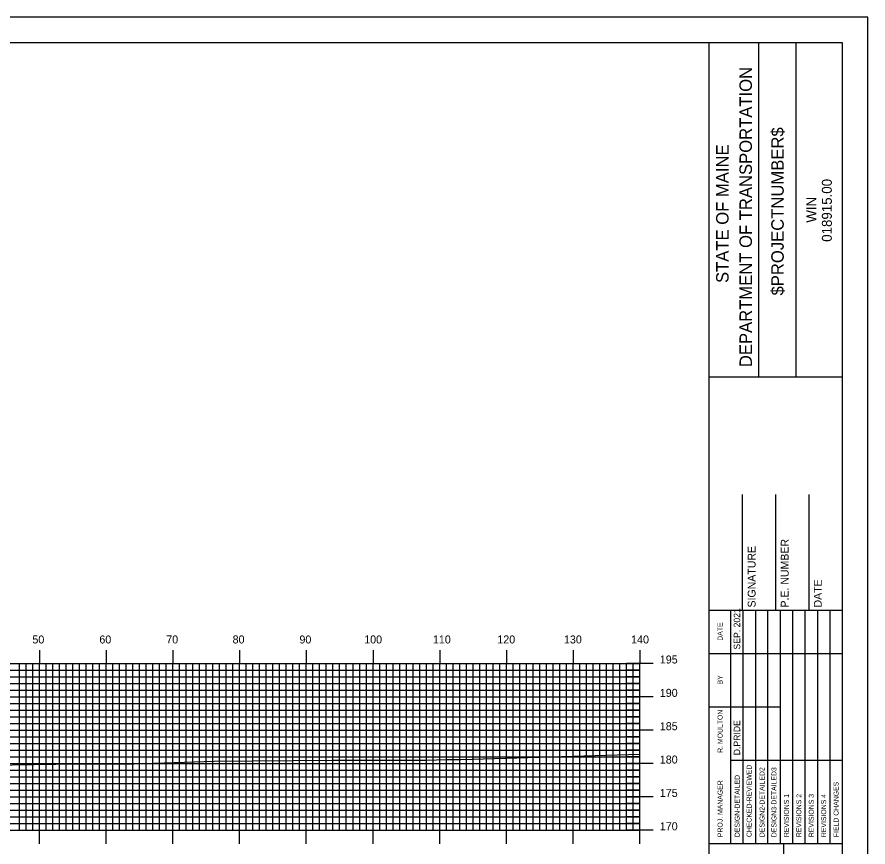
# Model space of a CAD drawing. Extents: x 1823573 to 1823916, y 442591 to 442811.
# Drawn here: x 1823784.9 to 1823912.5, y 442686.2 to 442810.5 of the extents above; entities that cross this region are included whole.
import ezdxf

# ---------------------------------------------------------------- set-up
doc = ezdxf.new("R2010")
doc.units = 0
for name, color, linetype in [('BORDER', 7, 'Continuous'), ('H_V ANNOTATION', 7, 'Continuous'), ('MAJOR', 7, 'Continuous'), ('MINOR', 7, 'Continuous'), ('PLOT BOUNDARY', 7, 'Continuous'), ('S_Roadway_Centerline', 7, 'Continuous')]:
    doc.layers.add(name, color=color, linetype=linetype)

msp = doc.modelspace()

# ---------------------------------------------------------------- linework, layer by layer
at = {"layer": 'BORDER'}
for p, q in [((1823888.71, 442596.67), (1823888.71, 442806.67)), ((1823896.17, 442756.66), (1823896.17, 442806.66)), ((1823901.76, 442756.66), (1823901.76, 442806.66)), ((1823888.71, 442756.65), (1823908.71, 442756.65)), ((1823893.71, 442721.67), (1823893.71, 442738.97)), ((1823898.71, 442721.67), (1823898.71, 442738.97)), ((1823903.71, 442721.67), (1823903.71, 442738.97)), ((1823888.71, 442721.67), (1823908.71, 442721.67)), ((1823888.71, 442686.67), (1823908.71, 442686.67)), ((1823899.89, 442616.67), (1823899.89, 442686.67))]:
    msp.add_line(p, q, dxfattribs=at)
msp.add_lwpolyline([(1823588.71, 442596.67), (1823908.71, 442596.67), (1823908.71, 442806.67), (1823588.71, 442806.67)], close=True, dxfattribs=at)
for points in [[(1823891.94, 442715.17), (1823891.94, 442721.67)], [(1823893.8, 442686.68), (1823893.8, 442721.67)], [(1823895.67, 442721.67), (1823895.67, 442686.68)], [(1823897.53, 442686.68), (1823897.53, 442721.67)], [(1823899.39, 442686.68), (1823899.39, 442721.67)], [(1823901.26, 442686.68), (1823901.26, 442721.67)], [(1823903.12, 442686.68), (1823903.12, 442721.67)], [(1823904.98, 442686.68), (1823904.98, 442721.67)], [(1823906.85, 442686.68), (1823906.85, 442721.67)], [(1823891.94, 442686.68), (1823891.94, 442720.26)], [(1823888.71, 442715.17), (1823908.71, 442715.17)], [(1823888.71, 442707.17), (1823891.94, 442707.17)], [(1823891.94, 442707.17), (1823899.39, 442707.17)], [(1823891.94, 442699.17), (1823908.71, 442699.17)]]:
    msp.add_lwpolyline(points, dxfattribs=at)
at = {"layer": 'MAJOR'}
for p, q in [((1823788.31, 442715.67), (1823788.31, 442713.67)), ((1823798.31, 442715.67), (1823798.31, 442713.67)), ((1823808.31, 442715.67), (1823808.31, 442713.67)), ((1823818.31, 442715.67), (1823818.31, 442713.67)), ((1823828.31, 442715.67), (1823828.31, 442713.67)), ((1823838.31, 442715.67), (1823838.31, 442713.67)), ((1823848.31, 442715.67), (1823848.31, 442713.67)), ((1823858.31, 442715.67), (1823858.31, 442713.67)), ((1823868.31, 442715.67), (1823868.31, 442713.67)), ((1823878.31, 442715.67), (1823878.31, 442713.67)), ((1823598.31, 442713.67), (1823878.31, 442713.67)), ((1823598.31, 442713.67), (1823878.31, 442713.67)), ((1823788.31, 442688.67), (1823788.31, 442713.67)), ((1823798.31, 442688.67), (1823798.31, 442713.67)), ((1823808.31, 442688.67), (1823808.31, 442713.67)), ((1823818.31, 442688.67), (1823818.31, 442713.67)), ((1823828.31, 442688.67), (1823828.31, 442713.67)), ((1823838.31, 442688.67), (1823838.31, 442713.67)), ((1823848.31, 442688.67), (1823848.31, 442713.67)), ((1823858.31, 442688.67), (1823858.31, 442713.67)), ((1823868.31, 442688.67), (1823868.31, 442713.67)), ((1823880.31, 442713.67), (1823876.3, 442713.67)), ((1823878.31, 442688.67), (1823878.31, 442713.67)), ((1823878.31, 442688.67), (1823878.31, 442713.67)), ((1823598.31, 442708.67), (1823878.31, 442708.67)), ((1823880.31, 442708.67), (1823876.3, 442708.67)), ((1823598.31, 442703.67), (1823878.31, 442703.67)), ((1823880.31, 442703.67), (1823876.3, 442703.67)), ((1823598.31, 442698.67), (1823878.31, 442698.67)), ((1823880.31, 442698.67), (1823876.3, 442698.67)), ((1823598.31, 442693.67), (1823878.31, 442693.67)), ((1823880.31, 442693.67), (1823876.3, 442693.67)), ((1823598.31, 442688.67), (1823878.31, 442688.67)), ((1823598.31, 442688.67), (1823878.31, 442688.67)), ((1823788.31, 442686.66), (1823788.31, 442688.67)), ((1823798.31, 442686.66), (1823798.31, 442688.67)), ((1823808.31, 442686.66), (1823808.31, 442688.67)), ((1823818.31, 442686.66), (1823818.31, 442688.67)), ((1823828.31, 442686.66), (1823828.31, 442688.67)), ((1823838.31, 442686.66), (1823838.31, 442688.67)), ((1823848.31, 442686.66), (1823848.31, 442688.67)), ((1823858.31, 442686.66), (1823858.31, 442688.67)), ((1823868.31, 442686.66), (1823868.31, 442688.67)), ((1823880.31, 442688.67), (1823876.3, 442688.67)), ((1823878.31, 442686.66), (1823878.31, 442688.67))]:
    msp.add_line(p, q, dxfattribs=at)
at = {"layer": 'MINOR'}
for p, q in [((1823785.31, 442688.67), (1823785.31, 442713.67)), ((1823786.31, 442688.67), (1823786.31, 442713.67)), ((1823787.31, 442688.67), (1823787.31, 442713.67)), ((1823789.31, 442688.67), (1823789.31, 442713.67)), ((1823790.31, 442688.67), (1823790.31, 442713.67)), ((1823791.31, 442688.67), (1823791.31, 442713.67)), ((1823792.31, 442688.67), (1823792.31, 442713.67)), ((1823793.31, 442688.67), (1823793.31, 442713.67)), ((1823794.31, 442688.67), (1823794.31, 442713.67)), ((1823795.31, 442688.67), (1823795.31, 442713.67)), ((1823796.31, 442688.67), (1823796.31, 442713.67)), ((1823797.31, 442688.67), (1823797.31, 442713.67)), ((1823799.31, 442688.67), (1823799.31, 442713.67)), ((1823800.31, 442688.67), (1823800.31, 442713.67)), ((1823801.31, 442688.67), (1823801.31, 442713.67)), ((1823802.31, 442688.67), (1823802.31, 442713.67)), ((1823803.31, 442688.67), (1823803.31, 442713.67)), ((1823804.31, 442688.67), (1823804.31, 442713.67)), ((1823805.31, 442688.67), (1823805.31, 442713.67)), ((1823806.31, 442688.67), (1823806.31, 442713.67)), ((1823807.31, 442688.67), (1823807.31, 442713.67)), ((1823809.31, 442688.67), (1823809.31, 442713.67)), ((1823810.31, 442688.67), (1823810.31, 442713.67)), ((1823811.31, 442688.67), (1823811.31, 442713.67)), ((1823812.31, 442688.67), (1823812.31, 442713.67)), ((1823813.31, 442688.67), (1823813.31, 442713.67)), ((1823814.31, 442688.67), (1823814.31, 442713.67)), ((1823815.31, 442688.67), (1823815.31, 442713.67)), ((1823816.31, 442688.67), (1823816.31, 442713.67)), ((1823817.31, 442688.67), (1823817.31, 442713.67)), ((1823819.31, 442688.67), (1823819.31, 442713.67)), ((1823820.31, 442688.67), (1823820.31, 442713.67)), ((1823821.31, 442688.67), (1823821.31, 442713.67)), ((1823822.31, 442688.67), (1823822.31, 442713.67)), ((1823823.31, 442688.67), (1823823.31, 442713.67)), ((1823824.31, 442688.67), (1823824.31, 442713.67)), ((1823825.31, 442688.67), (1823825.31, 442713.67)), ((1823826.31, 442688.67), (1823826.31, 442713.67)), ((1823827.31, 442688.67), (1823827.31, 442713.67)), ((1823829.31, 442688.67), (1823829.31, 442713.67)), ((1823830.31, 442688.67), (1823830.31, 442713.67)), ((1823831.31, 442688.67), (1823831.31, 442713.67)), ((1823832.31, 442688.67), (1823832.31, 442713.67)), ((1823833.31, 442688.67), (1823833.31, 442713.67)), ((1823834.31, 442688.67), (1823834.31, 442713.67)), ((1823835.31, 442688.67), (1823835.31, 442713.67)), ((1823836.31, 442688.67), (1823836.31, 442713.67)), ((1823837.31, 442688.67), (1823837.31, 442713.67)), ((1823839.31, 442688.67), (1823839.31, 442713.67)), ((1823840.31, 442688.67), (1823840.31, 442713.67)), ((1823841.31, 442688.67), (1823841.31, 442713.67)), ((1823842.31, 442688.67), (1823842.31, 442713.67)), ((1823843.31, 442688.67), (1823843.31, 442713.67)), ((1823844.31, 442688.67), (1823844.31, 442713.67)), ((1823845.31, 442688.67), (1823845.31, 442713.67)), ((1823846.31, 442688.67), (1823846.31, 442713.67)), ((1823847.31, 442688.67), (1823847.31, 442713.67)), ((1823849.31, 442688.67), (1823849.31, 442713.67)), ((1823850.31, 442688.67), (1823850.31, 442713.67)), ((1823851.31, 442688.67), (1823851.31, 442713.67)), ((1823852.31, 442688.67), (1823852.31, 442713.67)), ((1823853.31, 442688.67), (1823853.31, 442713.67)), ((1823854.31, 442688.67), (1823854.31, 442713.67)), ((1823855.31, 442688.67), (1823855.31, 442713.67)), ((1823856.31, 442688.67), (1823856.31, 442713.67)), ((1823857.31, 442688.67), (1823857.31, 442713.67)), ((1823859.31, 442688.67), (1823859.31, 442713.67)), ((1823860.31, 442688.67), (1823860.31, 442713.67)), ((1823861.31, 442688.67), (1823861.31, 442713.67)), ((1823862.31, 442688.67), (1823862.31, 442713.67)), ((1823863.31, 442688.67), (1823863.31, 442713.67)), ((1823864.31, 442688.67), (1823864.31, 442713.67)), ((1823865.31, 442688.67), (1823865.31, 442713.67)), ((1823866.31, 442688.67), (1823866.31, 442713.67)), ((1823867.31, 442688.67), (1823867.31, 442713.67)), ((1823869.31, 442688.67), (1823869.31, 442713.67)), ((1823870.31, 442688.67), (1823870.31, 442713.67)), ((1823871.31, 442688.67), (1823871.31, 442713.67)), ((1823872.31, 442688.67), (1823872.31, 442713.67)), ((1823873.31, 442688.67), (1823873.31, 442713.67)), ((1823874.31, 442688.67), (1823874.31, 442713.67)), ((1823875.31, 442688.67), (1823875.31, 442713.67)), ((1823876.31, 442688.67), (1823876.31, 442713.67)), ((1823877.31, 442688.67), (1823877.31, 442713.67)), ((1823598.31, 442712.67), (1823878.31, 442712.67)), ((1823878.31, 442712.67), (1823876.3, 442712.67)), ((1823598.31, 442711.67), (1823878.31, 442711.67)), ((1823878.31, 442711.67), (1823876.3, 442711.67)), ((1823598.31, 442710.67), (1823878.31, 442710.67)), ((1823878.31, 442710.67), (1823876.3, 442710.67)), ((1823598.31, 442709.67), (1823878.31, 442709.67)), ((1823878.31, 442709.67), (1823876.3, 442709.67)), ((1823598.31, 442707.67), (1823878.31, 442707.67)), ((1823878.31, 442707.67), (1823876.3, 442707.67)), ((1823598.31, 442706.67), (1823878.31, 442706.67)), ((1823878.31, 442706.67), (1823876.3, 442706.67)), ((1823598.31, 442705.67), (1823878.31, 442705.67)), ((1823878.31, 442705.67), (1823876.3, 442705.67)), ((1823598.31, 442704.67), (1823878.31, 442704.67)), ((1823878.31, 442704.67), (1823876.3, 442704.67)), ((1823598.31, 442702.67), (1823878.31, 442702.67)), ((1823878.31, 442702.67), (1823876.3, 442702.67)), ((1823598.31, 442701.67), (1823878.31, 442701.67)), ((1823878.31, 442701.67), (1823876.3, 442701.67)), ((1823598.31, 442700.67), (1823878.31, 442700.67)), ((1823598.31, 442699.67), (1823878.31, 442699.67)), ((1823878.31, 442700.67), (1823876.3, 442700.67)), ((1823878.31, 442699.67), (1823876.3, 442699.67)), ((1823598.31, 442697.67), (1823878.31, 442697.67)), ((1823878.31, 442697.67), (1823876.3, 442697.67)), ((1823598.31, 442696.67), (1823878.31, 442696.67)), ((1823878.31, 442696.67), (1823876.3, 442696.67)), ((1823598.31, 442695.67), (1823878.31, 442695.67)), ((1823598.31, 442694.67), (1823878.31, 442694.67)), ((1823878.31, 442695.67), (1823876.3, 442695.67)), ((1823878.31, 442694.67), (1823876.3, 442694.67)), ((1823598.31, 442692.67), (1823878.31, 442692.67)), ((1823878.31, 442692.67), (1823876.3, 442692.67)), ((1823598.31, 442691.67), (1823878.31, 442691.67)), ((1823598.31, 442690.67), (1823878.31, 442690.67)), ((1823878.31, 442691.67), (1823876.3, 442691.67)), ((1823878.31, 442690.67), (1823876.3, 442690.67)), ((1823598.31, 442689.67), (1823878.31, 442689.67)), ((1823878.31, 442689.67), (1823876.3, 442689.67))]:
    msp.add_line(p, q, dxfattribs=at)
at = {"layer": 'PLOT BOUNDARY'}
msp.add_lwpolyline([(1823572.52, 442590.55), (1823912.52, 442590.55), (1823912.52, 442810.55), (1823572.52, 442810.55)], close=True, dxfattribs=at)
at = {"layer": 'S_Roadway_Centerline'}
msp.add_lwpolyline([(1823774.36, 442698.35), (1823794.06, 442698.63), (1823802.46, 442698.65), (1823806.98, 442698.8), (1823814.5, 442699.01), (1823820.29, 442699.06), (1823832.15, 442699.2), (1823846.4, 442699.19), (1823849.29, 442699.26), (1823851.48, 442699.29), (1823878.31, 442700.1)], dxfattribs=at)

# ---------------------------------------------------------------- texts
at = {"layer": 'BORDER'}
for s, height, p in [('DEPARTMENT OF TRANSPORTATION', 1.8635, (1823895.12, 442758.08)), ('$PROJECTNUMBER$', 1.8635, (1823899.89, 442768.82)), ('STATE OF MAINE', 1.8635, (1823891.62, 442770.69)), ('018915.00', 1.491, (1823907.1, 442776.86)), ('WIN', 1.491, (1823904.78, 442779.73)), ('P.E. NUMBER', 1.1811, (1823900.63, 442722.06)), ('SIGNATURE', 1.181, (1823895.67, 442722.06)), ('DATE', 1.181, (1823905.59, 442722.06)), ('SEP. 2021', 0.969, (1823893.36, 442715.76)), ('DATE', 0.743, (1823890.72, 442717.08)), ('BY', 0.743, (1823890.72, 442710.54)), ('R. MOULTON', 0.745, (1823890.72, 442700.28)), ('D.PRIDE', 0.969, (1823893.36, 442699.92)), ('CHECKED-REVIEWED', 0.7455, (1823895.07, 442687.65)), ('DESIGN2-DETAILED2', 0.7455, (1823897.01, 442687.65)), ('DESIGN3-DETAILED3', 0.7455, (1823898.8, 442687.65)), ('PROJ. MANAGER', 0.7455, (1823890.72, 442687.65)), ('DESIGN-DETAILED', 0.7455, (1823893.28, 442687.65)), ('FIELD CHANGES', 0.7455, (1823908.11, 442687.65)), ('REVISIONS 1', 0.7455, (1823900.66, 442687.65)), ('REVISIONS 2', 0.7455, (1823902.52, 442687.65)), ('REVISIONS 3', 0.7455, (1823904.39, 442687.65)), ('REVISIONS 4', 0.7455, (1823906.25, 442687.65))]:
    msp.add_text(s, height=height, rotation=90, dxfattribs=at).set_placement(p)
at = {"layer": 'H_V ANNOTATION'}
for s, p in [('50', (1823787.24, 442716.67)), ('60', (1823797.28, 442716.67)), ('70', (1823807.31, 442716.67)), ('80', (1823817.26, 442716.67)), ('90', (1823827.28, 442716.67)), ('100', (1823836.99, 442716.67)), ('110', (1823847.29, 442716.67)), ('120', (1823856.95, 442716.67)), ('130', (1823866.94, 442716.67)), ('140', (1823877.01, 442716.67)), ('195', (1823881.31, 442713.67)), ('190', (1823881.31, 442708.67)), ('185', (1823881.31, 442703.67)), ('180', (1823881.31, 442698.67)), ('175', (1823881.31, 442693.67)), ('170', (1823881.31, 442688.67))]:
    msp.add_text(s, height=1.2, dxfattribs=at).set_placement(p)

doc.saveas('drawing.dxf')
